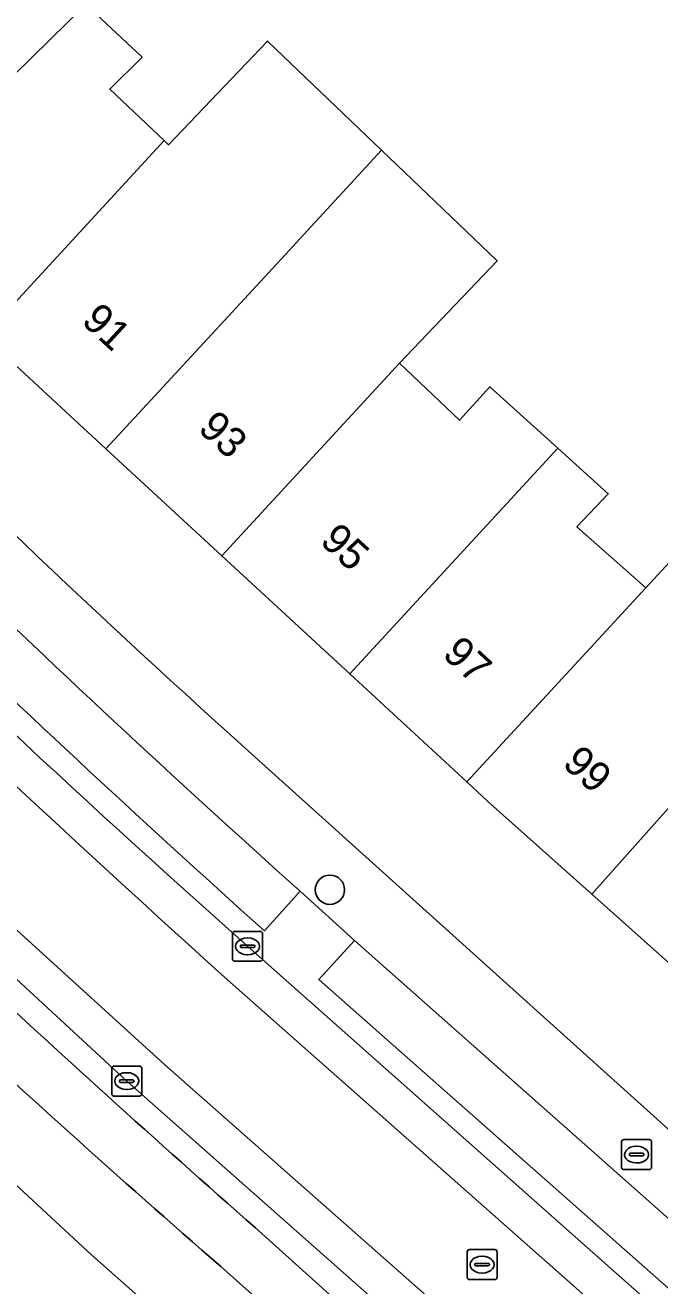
# Model space of a CAD drawing. Extents: x 162073 to 163043, y 381818 to 382561.
# Drawn here: x 162603.55 to 162624.75, y 382205.18 to 382247.25 of the extents above; entities that cross this region are included whole.
import ezdxf

# ---------------------------------------------------------------- set-up
doc = ezdxf.new("R2010")
doc.units = 0
for name, color, linetype in [('IMGEO_Boom', 7, 'Continuous'), ('IMGEO_Brandkraan', 7, 'Continuous'), ('IMGEO_Erf', 7, 'Continuous'), ('IMGEO_Fietspad_gesloten', 7, 'Continuous'), ('IMGEO_Kolk', 7, 'Continuous'), ('IMGEO_Pand', 7, 'Continuous'), ('IMGEO_Pand_nummerreeks', 7, 'Continuous'), ('IMGEO_Parkeervlak_open', 7, 'Continuous'), ('IMGEO_Rijbaan_lokaal_open', 7, 'Continuous'), ('IMGEO_Rioolput', 7, 'Continuous'), ('IMGEO_Voetpad_open', 7, 'Continuous')]:
    doc.layers.add(name, color=color, linetype=linetype)

msp = doc.modelspace()

# ---------------------------------------------------------------- linework, layer by layer
at = {"layer": 'IMGEO_Boom'}
msp.add_circle((162613.73, 382218.4), 0.489, dxfattribs=at)
at = {"layer": 'IMGEO_Brandkraan'}
for p, q in [((162623.546, 382210.06), (162624.398, 382210.06)), ((162623.471, 382209.134), (162623.471, 382209.986)), ((162623.773, 382209.603), (162624.171, 382209.603)), ((162623.959, 382209.84), (162623.984, 382209.84)), ((162624.472, 382209.986), (162624.472, 382209.134)), ((162623.73, 382209.554), (162623.73, 382209.566)), ((162624.168, 382209.517), (162623.77, 382209.517)), ((162623.982, 382209.28), (162623.957, 382209.28)), ((162624.214, 382209.566), (162624.214, 382209.554)), ((162624.398, 382209.06), (162623.546, 382209.06))]:
    msp.add_line(p, q, dxfattribs=at)
for points in [[(162623.546, 382210.06), (162624.398, 382210.06)], [(162623.471, 382209.134), (162623.471, 382209.986)], [(162624.472, 382209.986), (162624.472, 382209.134)], [(162624.398, 382209.06), (162623.546, 382209.06)]]:
    msp.add_lwpolyline(points, dxfattribs=at)
for centre, radius, start, end in [((162623.548, 382209.984), 0.0765, 91.552, 178.448), ((162623.548, 382209.984), 0.0765, 91.552, 178.448), ((162624.396, 382209.984), 0.0765, 1.552, 88.448), ((162624.396, 382209.984), 0.0765, 1.552, 88.448), ((162623.77, 382209.563), 0.0403, 85.8775, 175.7526), ((162624.175, 382209.565), 0.0386, 1.7309, 96.639), ((162623.767, 382209.553), 0.0366, 178.938, 274.7102), ((162624.171, 382209.56), 0.043, 264.8664, 352.4533), ((162623.548, 382209.136), 0.0765, 181.552, 268.448), ((162623.548, 382209.136), 0.0765, 181.552, 268.448), ((162624.396, 382209.136), 0.0765, 271.552, 358.448), ((162624.396, 382209.136), 0.0765, 271.552, 358.448)]:
    msp.add_arc(centre, radius, start, end, dxfattribs=at)
for centre, major_axis, ratio, start_param, end_param in [((162623.958, 382209.56), (-0.387, 0.002), 0.722429, 4.712389, 7.853982), ((162623.983, 382209.56), (-0.39, 0.002), 0.717154, 1.570796, 4.712389)]:
    msp.add_ellipse(centre, major_axis=major_axis, ratio=ratio, start_param=start_param, end_param=end_param, dxfattribs=at)
at = {"layer": 'IMGEO_Erf'}
for points in [[(162610.12, 382229.543), (162606.25, 382233.112), (162602.17, 382236.876), (162602.004, 382237.029), (162598.298, 382240.814), (162594.439, 382244.754), (162590.699, 382248.574), (162589.303, 382250), (162586.974, 382252.616), (162583.214, 382256.841), (162580.144, 382254.147), (162583.782, 382250), (162595.326, 382237.974)], [(162605.58, 382247.945), (162607.455, 382246.187), (162606.38, 382245.123), (162608.195, 382243.405), (162608.343, 382243.264), (162611.645, 382246.722), (162615.452, 382243.086), (162619.318, 382239.393), (162616.058, 382235.98), (162618.06, 382234.069), (162619.065, 382235.182), (162621.341, 382233.133), (162623.024, 382231.618), (162621.979, 382230.514), (162624.277, 382228.477), (162626.929, 382231.351), (162630.935, 382227.781), (162630.765, 382227.574), (162634.815, 382224.018), (162638.997, 382220.344), (162638.043, 382219.258), (162636.635, 382217.655), (162633.334, 382213.898), (162692.173, 382161.844)], [(162610.896, 382223.128), (162627.91, 382207.821), (162630.71, 382210.912), (162626.487, 382214.676), (162622.476, 382218.253), (162618.996, 382221.355), (162618.298, 382221.998), (162614.393, 382225.601), (162610.12, 382229.543)]]:
    msp.add_lwpolyline(points, dxfattribs=at)
msp.add_lwpolyline([(162592.043, 382218.91), (162584.822, 382225.942), (162573.298, 382238.041), (162570.341, 382235.295), (162574.035, 382231.214), (162577.783, 382227.419), (162581.647, 382223.506), (162585.757, 382219.345), (162586.991, 382218.096), (162589.637, 382215.563), (162592.295, 382213.017), (162593.539, 382211.887), (162597.618, 382208.184), (162601.869, 382204.326), (162606.169, 382200.422), (162606.685, 382199.954), (162610.219, 382196.821), (162614.278, 382193.221), (162618.589, 382189.398), (162621.309, 382192.475), (162605.774, 382206.205)], close=True, dxfattribs=at)
msp.add_arc((162863.176, 382503.298), 377.015, 224.72862, 227.99851, dxfattribs=at)
at = {"layer": 'IMGEO_Fietspad_gesloten'}
for points in [[(162601.77, 382216.788), (162606.944, 382212.014), (162640.048, 382182.752), (162640.86, 382183.603), (162628.624, 382194.55), (162608.204, 382212.566), (162602.641, 382217.615)], [(162610.213, 382215.487), (162643.217, 382186.312), (162644.019, 382187.212), (162624.584, 382204.454), (162610.981, 382216.511)]]:
    msp.add_lwpolyline(points, dxfattribs=at)
for centre, radius, start, end in [((162911.998, 382552.033), 452.037, 222.06113, 228.11702), ((162884.404, 382524.721), 412.011, 222.02105, 228.42275)]:
    msp.add_arc(centre, radius, start, end, dxfattribs=at)
at = {"layer": 'IMGEO_Kolk'}
for p, q in [((162610.48, 382216.085), (162610.48, 382216.937)), ((162610.555, 382217.011), (162611.407, 382217.011)), ((162610.968, 382216.791), (162610.993, 382216.791)), ((162611.481, 382216.937), (162611.481, 382216.085)), ((162610.739, 382216.505), (162610.739, 382216.517)), ((162611.177, 382216.468), (162610.779, 382216.468)), ((162610.782, 382216.554), (162611.18, 382216.554)), ((162611.223, 382216.517), (162611.223, 382216.505)), ((162611.407, 382216.011), (162610.555, 382216.011)), ((162610.991, 382216.231), (162610.966, 382216.231)), ((162606.443, 382211.588), (162606.443, 382212.44)), ((162606.518, 382212.514), (162607.37, 382212.514)), ((162606.931, 382212.294), (162606.956, 382212.294)), ((162607.444, 382212.44), (162607.444, 382211.588)), ((162606.702, 382212.008), (162606.702, 382212.02)), ((162607.14, 382211.971), (162606.742, 382211.971)), ((162606.745, 382212.057), (162607.143, 382212.057)), ((162606.954, 382211.734), (162606.929, 382211.734)), ((162607.186, 382212.02), (162607.186, 382212.008)), ((162607.37, 382211.514), (162606.518, 382211.514))]:
    msp.add_line(p, q, dxfattribs=at)
for points in [[(162610.48, 382216.085), (162610.48, 382216.937)], [(162610.555, 382217.011), (162611.407, 382217.011)], [(162611.481, 382216.937), (162611.481, 382216.085)], [(162611.407, 382216.011), (162610.555, 382216.011)], [(162606.443, 382211.588), (162606.443, 382212.44)], [(162606.518, 382212.514), (162607.37, 382212.514)], [(162607.444, 382212.44), (162607.444, 382211.588)], [(162607.37, 382211.514), (162606.518, 382211.514)]]:
    msp.add_lwpolyline(points, dxfattribs=at)
for centre, radius, start, end in [((162610.557, 382216.935), 0.0765, 91.552, 178.448), ((162610.557, 382216.935), 0.0765, 91.552, 178.448), ((162611.405, 382216.935), 0.0765, 1.552, 88.448), ((162611.405, 382216.935), 0.0765, 1.552, 88.448), ((162610.779, 382216.514), 0.0403, 85.8775, 175.7526), ((162610.776, 382216.504), 0.0366, 178.938, 274.7102), ((162611.18, 382216.511), 0.043, 264.8664, 352.4533), ((162611.184, 382216.516), 0.0386, 1.7309, 96.639), ((162610.557, 382216.087), 0.0765, 181.552, 268.448), ((162610.557, 382216.087), 0.0765, 181.552, 268.448), ((162611.405, 382216.087), 0.0765, 271.552, 358.448), ((162611.405, 382216.087), 0.0765, 271.552, 358.448), ((162606.52, 382212.438), 0.0765, 91.552, 178.448), ((162606.52, 382212.438), 0.0765, 91.552, 178.448), ((162607.368, 382212.438), 0.0765, 1.552, 88.448), ((162607.368, 382212.438), 0.0765, 1.552, 88.448), ((162606.742, 382212.017), 0.0403, 85.8775, 175.7526), ((162606.739, 382212.007), 0.0366, 178.938, 274.7102), ((162607.143, 382212.014), 0.043, 264.8664, 352.4533), ((162607.147, 382212.019), 0.0386, 1.7309, 96.639), ((162606.52, 382211.59), 0.0765, 181.552, 268.448), ((162606.52, 382211.59), 0.0765, 181.552, 268.448), ((162607.368, 382211.59), 0.0765, 271.552, 358.448), ((162607.368, 382211.59), 0.0765, 271.552, 358.448)]:
    msp.add_arc(centre, radius, start, end, dxfattribs=at)
for centre, major_axis, ratio, start_param, end_param in [((162610.967, 382216.511), (-0.387, 0.002), 0.722429, 4.712389, 7.853982), ((162610.992, 382216.511), (-0.39, 0.002), 0.717154, 1.570796, 4.712389), ((162606.93, 382212.014), (-0.387, 0.002), 0.722429, 4.712389, 7.853982), ((162606.955, 382212.014), (-0.39, 0.002), 0.717154, 1.570796, 4.712389)]:
    msp.add_ellipse(centre, major_axis=major_axis, ratio=ratio, start_param=start_param, end_param=end_param, dxfattribs=at)
at = {"layer": 'IMGEO_Pand'}
for points in [[(162598.298, 382240.814), (162605.58, 382247.945), (162603.389, 382250), (162602.379, 382249.007), (162601.453, 382250), (162600.663, 382250.848), (162599.797, 382250), (162594.439, 382244.754)], [(162602.17, 382236.876), (162608.195, 382243.405), (162606.38, 382245.123), (162607.455, 382246.187), (162605.58, 382247.945), (162598.298, 382240.814), (162602.004, 382237.029)], [(162615.452, 382243.086), (162611.645, 382246.722), (162608.343, 382243.264), (162608.195, 382243.405), (162602.17, 382236.876), (162606.25, 382233.112), (162612.23, 382239.594), (162613.234, 382240.682)], [(162616.058, 382235.98), (162619.318, 382239.393), (162615.452, 382243.086), (162613.234, 382240.682), (162612.23, 382239.594), (162606.25, 382233.112), (162610.12, 382229.543)], [(162616.058, 382235.98), (162610.12, 382229.543), (162614.393, 382225.601), (162621.341, 382233.133), (162619.065, 382235.182), (162618.06, 382234.069)], [(162621.341, 382233.133), (162614.393, 382225.601), (162618.298, 382221.998), (162624.277, 382228.477), (162621.979, 382230.514), (162623.024, 382231.618)], [(162629.366, 382225.981), (162630.765, 382227.574), (162630.935, 382227.781), (162626.929, 382231.351), (162624.277, 382228.477), (162618.298, 382221.998), (162618.996, 382221.355), (162622.476, 382218.253)], [(162622.476, 382218.253), (162626.487, 382214.676), (162632.309, 382221.207), (162634.815, 382224.018), (162630.765, 382227.574), (162629.366, 382225.981)]]:
    msp.add_lwpolyline(points, close=True, dxfattribs=at)
at = {"layer": 'IMGEO_Parkeervlak_open'}
for points in [[(162611.547, 382217.024), (162612.735, 382218.35)], [(162610.404, 382205.549), (162621.039, 382196.059), (162622.118, 382197.321), (162611.241, 382207.115)]]:
    msp.add_lwpolyline(points, dxfattribs=at)
msp.add_lwpolyline([(162626.433, 382206.191), (162614.546, 382216.706), (162613.365, 382215.409), (162625.089, 382205.044), (162658.585, 382175.454), (162659.783, 382176.802)], close=True, dxfattribs=at)
for centre, radius, start, end in [((162909.77, 382549.829), 445.094, 223.79118, 228.13678), ((162910.177, 382550.236), 447.449, 223.7962, 228.13278), ((162938.18, 382578.874), 495.07, 225.61314, 228.67039), ((162878.307, 382514.493), 408.924, 225.30387, 229.06957)]:
    msp.add_arc(centre, radius, start, end, dxfattribs=at)
at = {"layer": 'IMGEO_Rijbaan_lokaal_open'}
msp.add_lwpolyline([(162602.641, 382217.615), (162608.204, 382212.566), (162628.624, 382194.55), (162640.86, 382183.603), (162643.217, 382186.312), (162610.213, 382215.487)], dxfattribs=at)
msp.add_arc((162911.998, 382552.033), 452.037, 222.06113, 228.11702, dxfattribs=at)
at = {"layer": 'IMGEO_Rioolput'}
for p, q in [((162618.312, 382205.461), (162618.312, 382206.313)), ((162618.387, 382206.387), (162619.239, 382206.387)), ((162619.313, 382206.313), (162619.313, 382205.461)), ((162618.571, 382205.881), (162618.571, 382205.893)), ((162619.009, 382205.844), (162618.611, 382205.844)), ((162618.614, 382205.93), (162619.012, 382205.93)), ((162618.8, 382206.167), (162618.825, 382206.167)), ((162619.055, 382205.893), (162619.055, 382205.881)), ((162619.239, 382205.387), (162618.387, 382205.387)), ((162618.823, 382205.607), (162618.798, 382205.607))]:
    msp.add_line(p, q, dxfattribs=at)
for points in [[(162618.312, 382205.461), (162618.312, 382206.313)], [(162618.387, 382206.387), (162619.239, 382206.387)], [(162619.313, 382206.313), (162619.313, 382205.461)], [(162619.239, 382205.387), (162618.387, 382205.387)]]:
    msp.add_lwpolyline(points, dxfattribs=at)
for centre, radius, start, end in [((162618.389, 382206.311), 0.0765, 91.552, 178.448), ((162618.389, 382206.311), 0.0765, 91.552, 178.448), ((162619.237, 382206.311), 0.0765, 1.552, 88.448), ((162619.237, 382206.311), 0.0765, 1.552, 88.448), ((162618.611, 382205.89), 0.0403, 85.8775, 175.7526), ((162618.608, 382205.88), 0.0366, 178.938, 274.7102), ((162619.012, 382205.887), 0.043, 264.8664, 352.4533), ((162619.016, 382205.892), 0.0386, 1.7309, 96.639), ((162618.389, 382205.463), 0.0765, 181.552, 268.448), ((162618.389, 382205.463), 0.0765, 181.552, 268.448), ((162619.237, 382205.463), 0.0765, 271.552, 358.448), ((162619.237, 382205.463), 0.0765, 271.552, 358.448)]:
    msp.add_arc(centre, radius, start, end, dxfattribs=at)
for centre, major_axis, ratio, start_param, end_param in [((162618.799, 382205.887), (-0.387, 0.002), 0.722429, 4.712389, 7.853982), ((162618.824, 382205.887), (-0.39, 0.002), 0.717154, 1.570796, 4.712389)]:
    msp.add_ellipse(centre, major_axis=major_axis, ratio=ratio, start_param=start_param, end_param=end_param, dxfattribs=at)
at = {"layer": 'IMGEO_Voetpad_open'}
for points in [[(162515.515, 382317.726), (162524.856, 382301.801), (162530.981, 382292.245), (162532.058, 382290.664), (162540.59, 382278.138), (162545.965, 382270.851), (162557.981, 382255.464), (162562.574, 382250), (162567.838, 382244.089), (162572.157, 382239.239), (162572.556, 382238.82), (162573.298, 382238.041), (162584.822, 382225.942), (162592.043, 382218.91), (162605.774, 382206.205), (162621.309, 382192.475), (162624.656, 382189.517), (162626.716, 382187.697), (162638.741, 382177.42), (162641.717, 382174.636)], [(162663.448, 382176.799), (162650.98, 382187.783), (162646.961, 382191.28), (162631.425, 382205.025), (162627.91, 382207.821), (162610.896, 382223.128)], [(162610.981, 382216.511), (162624.584, 382204.454), (162644.019, 382187.212), (162658.031, 382174.847), (162658.585, 382175.454), (162625.089, 382205.044), (162613.365, 382215.409), (162614.546, 382216.706), (162612.735, 382218.35), (162611.547, 382217.024)], [(162612.735, 382218.35), (162614.546, 382216.706), (162626.433, 382206.191), (162659.783, 382176.802), (162658.585, 382175.454), (162658.031, 382174.847), (162659.768, 382173.314), (162663.777, 382169.764), (162667.189, 382173.499), (162663.448, 382176.799)], [(162640.817, 382182.048), (162640.048, 382182.752), (162606.944, 382212.014), (162601.77, 382216.788)], [(162611.241, 382207.115), (162622.118, 382197.321), (162621.039, 382196.059)], [(162621.039, 382196.059), (162610.404, 382205.549)]]:
    msp.add_lwpolyline(points, dxfattribs=at)
for centre, radius, start, end in [((162884.404, 382524.721), 412.011, 222.02105, 228.42275), ((162909.77, 382549.829), 445.094, 223.79118, 228.13678), ((162910.177, 382550.236), 447.449, 223.7962, 228.13278), ((162863.176, 382503.298), 377.015, 224.72862, 227.99851), ((162938.18, 382578.874), 495.07, 225.61314, 228.67039), ((162878.307, 382514.493), 408.924, 225.30387, 229.06957)]:
    msp.add_arc(centre, radius, start, end, dxfattribs=at)

# ---------------------------------------------------------------- texts
at = {"layer": 'IMGEO_Pand_nummerreeks'}
for s, rotation, p in [('91', 317.3089, (162605.394, 382237.331)), ('93', 317.3146, (162609.286, 382233.74)), ('95', 317.3073, (162613.358, 382229.985)), ('97', 317.3102, (162617.447, 382226.212)), ('99', 318.1168, (162621.454, 382222.554))]:
    msp.add_text(s, height=1, rotation=rotation, dxfattribs=at).set_placement(p)

doc.saveas('drawing.dxf')
